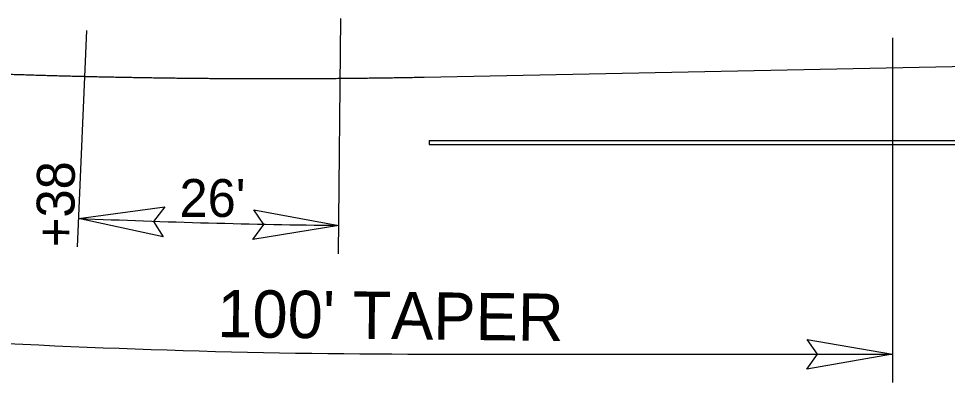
# Model space of a CAD drawing. Extents: x 1616561 to 1622460, y 896726 to 899651.
# Drawn here: x 1619756.7 to 1619854.8, y 897979.1 to 898017.5 of the extents above; entities that cross this region are included whole.
import ezdxf

# ---------------------------------------------------------------- set-up
doc = ezdxf.new("R2010")
doc.units = 0
for name, color, linetype in [('Prop Dimension', 7, 'Continuous'), ('Prop Guardrail', 7, 'Continuous'), ('Prop Terminator CELL', 7, 'Continuous'), ('Raster_Level_0', 7, 'Continuous'), ('Sheet Sticker Preliminary CELL', 7, 'Continuous')]:
    doc.layers.add(name, color=color, linetype=linetype)

msp = doc.modelspace()

# ---------------------------------------------------------------- linework, layer by layer
at = {"layer": 'Prop Dimension'}
for p, q in [((1619848.985, 898015.491), (1619848.985, 897979.076)), ((1619799.514, 897982.076), (1619848.985, 897982.076))]:
    msp.add_line(p, q, dxfattribs=at)
msp.add_arc((1619799.514, 898841.241), 859.164, 266.381188, 270, dxfattribs=at)
at = {"layer": 'Prop Guardrail'}
msp.add_line((1619799.514, 898011.347), (1619881.707, 898012.991), dxfattribs=at)
msp.add_spline([(1619747.618, 898011.969), (1619749.021, 898011.909), (1619749.722, 898011.881), (1619750.423, 898011.852), (1619751.125, 898011.825), (1619751.826, 898011.798), (1619752.527, 898011.771), (1619753.229, 898011.745), (1619753.93, 898011.72), (1619754.631, 898011.695), (1619755.333, 898011.671), (1619756.034, 898011.648), (1619756.735, 898011.625), (1619757.437, 898011.602), (1619758.138, 898011.581), (1619758.839, 898011.559), (1619759.541, 898011.539), (1619760.242, 898011.519), (1619760.943, 898011.5), (1619761.645, 898011.481), (1619762.346, 898011.463), (1619763.048, 898011.445), (1619763.749, 898011.428), (1619764.451, 898011.412), (1619765.152, 898011.396), (1619765.853, 898011.381), (1619766.555, 898011.366), (1619767.256, 898011.352), (1619767.958, 898011.338), (1619768.659, 898011.326), (1619769.36, 898011.313), (1619770.062, 898011.302), (1619770.763, 898011.291), (1619771.465, 898011.28), (1619772.166, 898011.27), (1619772.867, 898011.261), (1619773.569, 898011.252), (1619774.27, 898011.244), (1619774.972, 898011.237), (1619775.673, 898011.23), (1619776.374, 898011.223), (1619777.076, 898011.218), (1619777.777, 898011.212), (1619778.479, 898011.208), (1619779.18, 898011.204), (1619779.881, 898011.201), (1619780.583, 898011.198), (1619781.284, 898011.196), (1619781.985, 898011.194), (1619782.687, 898011.193), (1619783.388, 898011.193), (1619784.089, 898011.193), (1619784.79, 898011.194), (1619785.492, 898011.195), (1619786.193, 898011.197), (1619786.894, 898011.199), (1619787.595, 898011.203), (1619788.297, 898011.206), (1619788.998, 898011.211), (1619789.699, 898011.216), (1619790.4, 898011.221), (1619791.101, 898011.227), (1619791.802, 898011.234), (1619792.503, 898011.241), (1619793.205, 898011.249), (1619793.906, 898011.258), (1619794.607, 898011.267), (1619795.308, 898011.276), (1619796.009, 898011.287), (1619796.71, 898011.297), (1619797.411, 898011.309), (1619798.112, 898011.321), (1619798.813, 898011.334), (1619799.514, 898011.347)], degree=3, dxfattribs=at)
at = {"layer": 'Prop Terminator CELL'}
for points in [[(1619771.953, 897994.483), (1619763.028, 897996.42), (1619772.139, 897997.628), (1619770.921, 897996.079)], [(1619781.516, 897997.326), (1619790.499, 897995.681), (1619781.433, 897994.177), (1619782.6, 897995.765)], [(1619839.985, 897983.626), (1619848.985, 897982.076), (1619839.935, 897980.476), (1619841.085, 897982.076)]]:
    msp.add_lwpolyline(points, close=True, dxfattribs=at)
at = {"layer": 'Raster_Level_0'}
for p, q in [((1619800.042, 898004.657), (1619907.594, 898004.657)), ((1619800.042, 898004.657), (1619800.042, 898004.241)), ((1619800.042, 898004.241), (1619908.042, 898004.241))]:
    msp.add_line(p, q, dxfattribs=at)
at = {"layer": 'Sheet Sticker Preliminary CELL'}
for p, q in [((1619790.467, 897992.681), (1619790.732, 898017.537)), ((1619762.899, 897993.423), (1619763.885, 898016.26))]:
    msp.add_line(p, q, dxfattribs=at)
msp.add_arc((1619799.514, 898841.241), 845.608, 267.527103, 269.389216, dxfattribs=at)

# ---------------------------------------------------------------- texts
at = {"layer": 'Prop Dimension'}
msp.add_text("100' TAPER", height=5, rotation=359.33586, dxfattribs=at).set_placement((1619777.643, 897983.871))
at = {"layer": 'Sheet Sticker Preliminary CELL'}
for s, rotation, p in [('+38', 89.51505, (1619762.557, 897993.372)), ("26'", 359.88045, (1619773.674, 897996.579))]:
    msp.add_text(s, height=4, rotation=rotation, dxfattribs=at).set_placement(p)

doc.saveas('drawing.dxf')
